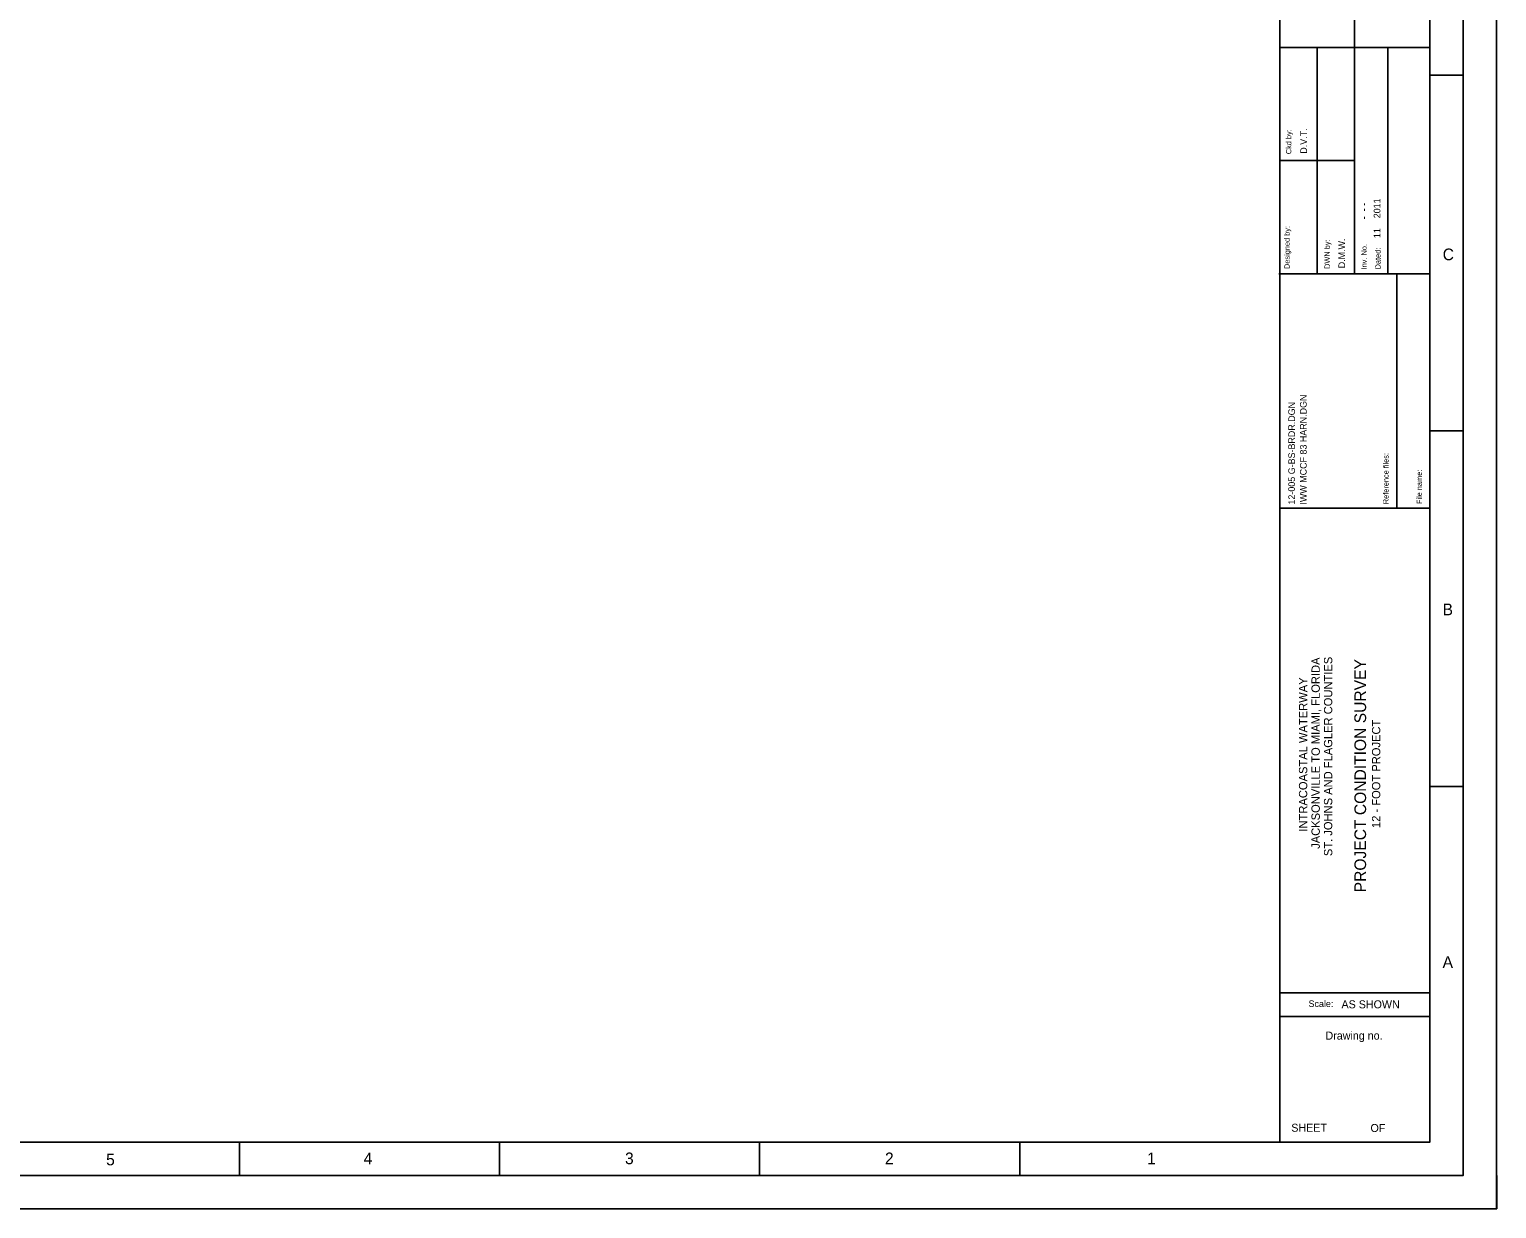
# Model space of a CAD drawing. Extents: x 1945213.1 to 1945257.1, y 2038820.4 to 2038854.4.
# Drawn here: x 1945235.14 to 1945257.14, y 2038820.38 to 2038838.07 of the extents above; entities that cross this region are included whole.
import ezdxf

# ---------------------------------------------------------------- set-up
doc = ezdxf.new("R2010")
doc.units = 0
for name, color, linetype in [('G-ANNO-NPLT', 7, 'Continuous'), ('G-ANNO-TEXT-DRWG', 7, 'Continuous'), ('G-ANNO-TEXT-PROJ', 7, 'Continuous'), ('G-ANNO-TEXT-TTLB', 7, 'Continuous'), ('G-ANNO-TTLB', 7, 'Continuous')]:
    doc.layers.add(name, color=color, linetype=linetype)

msp = doc.modelspace()

# ---------------------------------------------------------------- linework, layer by layer
at = {"layer": 'G-ANNO-NPLT'}
msp.add_lwpolyline([(1945213.137, 2038854.377), (1945257.137, 2038854.377), (1945257.137, 2038820.377), (1945213.137, 2038820.377)], close=True, dxfattribs=at)
msp.add_lwpolyline([(1945257.139, 2038820.877), (1945257.139, 2038820.377), (1945256.639, 2038820.377)], dxfattribs=at)
at = {"layer": 'G-ANNO-TTLB'}
for p, q in [((1945253.887, 2038853.377), (1945253.887, 2038821.377)), ((1945255.006, 2038834.399), (1945255.012, 2038842.994)), ((1945253.879, 2038837.795), (1945256.137, 2038837.795)), ((1945254.446, 2038834.399), (1945254.449, 2038837.795)), ((1945255.508, 2038837.795), (1945255.508, 2038834.399)), ((1945256.637, 2038837.376), (1945256.137, 2038837.376)), ((1945253.879, 2038836.097), (1945255.007, 2038836.097)), ((1945253.875, 2038834.399), (1945256.137, 2038834.399)), ((1945255.644, 2038834.399), (1945255.644, 2038830.885)), ((1945256.637, 2038832.043), (1945256.137, 2038832.043)), ((1945253.887, 2038830.885), (1945256.137, 2038830.885)), ((1945256.637, 2038826.71), (1945256.137, 2038826.71)), ((1945253.887, 2038823.615), (1945256.137, 2038823.615)), ((1945253.887, 2038823.258), (1945256.137, 2038823.258)), ((1945238.287, 2038820.877), (1945238.287, 2038821.377)), ((1945242.187, 2038820.877), (1945242.187, 2038821.377)), ((1945246.087, 2038820.877), (1945246.087, 2038821.377)), ((1945249.987, 2038820.877), (1945249.987, 2038821.377))]:
    msp.add_line(p, q, dxfattribs=at)
for points in [[(1945213.637, 2038820.877), (1945256.637, 2038820.877), (1945256.637, 2038853.877), (1945213.637, 2038853.877)], [(1945256.137, 2038853.377), (1945214.887, 2038853.377), (1945214.887, 2038821.377), (1945256.137, 2038821.377)]]:
    msp.add_lwpolyline(points, close=True, dxfattribs=at)

# ---------------------------------------------------------------- texts
at = {"layer": 'G-ANNO-TEXT-DRWG'}
for s, height, p in [('12-005 G-BS-BRDR.DGN                ', 0.1, (1945254.115, 2038830.938)), ('IWW MCCF 83 HARN.DGN                ', 0.1, (1945254.29, 2038830.938)), ('         JACKSONVILLE TO MIAMI, FLORIDA        ', 0.125, (1945254.487, 2038825.356)), ('        ST. JOHNS AND FLAGLER COUNTIES         ', 0.125, (1945254.674, 2038825.293)), ('      PROJECT CONDITION SURVEY     ', 0.175, (1945255.181, 2038824.732)), ('             INTRACOASTAL WATERWAY             ', 0.125, (1945254.299, 2038825.429)), ('                  12 - FOOT PROJECT                  ', 0.125, (1945255.394, 2038825.25))]:
    msp.add_text(s, height=height, rotation=90, dxfattribs=at).set_placement(p)
at = {"layer": 'G-ANNO-TEXT-PROJ'}
for s, p in [('D.V.T.      ', (1945254.294, 2038836.2)), ('11    2011', (1945255.395, 2038834.934)), ('      -  - -    ', (1945255.196, 2038834.994)), ('D.M.W.      ', (1945254.866, 2038834.482))]:
    msp.add_text(s, height=0.1, rotation=90, dxfattribs=at).set_placement(p)
at = {"layer": 'G-ANNO-TEXT-TTLB'}
for s, height, rotation, p in [('Ckd by:', 0.08, 90, (1945254.06, 2038836.192)), ('Designed by:', 0.08, 90, (1945254.035, 2038834.471)), ('DWN by:', 0.08, 90, (1945254.637, 2038834.472)), ('Inv. No.', 0.08, 90, (1945255.19, 2038834.464)), ('Dated:', 0.08, 90, (1945255.398, 2038834.465)), ('Reference files:', 0.08, 90, (1945255.518, 2038830.943)), ('File name:', 0.08, 90, (1945256.018, 2038830.945)), ('Scale:', 0.1, 360, (1945254.318, 2038823.401)), ('AS SHOWN', 0.12, 360, (1945254.812, 2038823.382)), ('Drawing no.', 0.12, 360, (1945254.572, 2038822.913)), ('SHEET', 0.12, 360, (1945254.059, 2038821.531)), ('OF', 0.12, 360, (1945255.247, 2038821.527))]:
    msp.add_text(s, height=height, rotation=rotation, dxfattribs=at).set_placement(p)
at = {"layer": 'G-ANNO-TTLB'}
for s, p in [('C', (1945256.33, 2038834.602)), ('B', (1945256.328, 2038829.277)), ('A', (1945256.328, 2038823.989)), ('5', (1945236.289, 2038821.027)), ('4', (1945240.151, 2038821.044)), ('3', (1945244.069, 2038821.044)), ('2', (1945247.967, 2038821.044)), ('1', (1945251.898, 2038821.044))]:
    msp.add_text(s, height=0.175, rotation=360, dxfattribs=at).set_placement(p)

doc.saveas('drawing.dxf')
